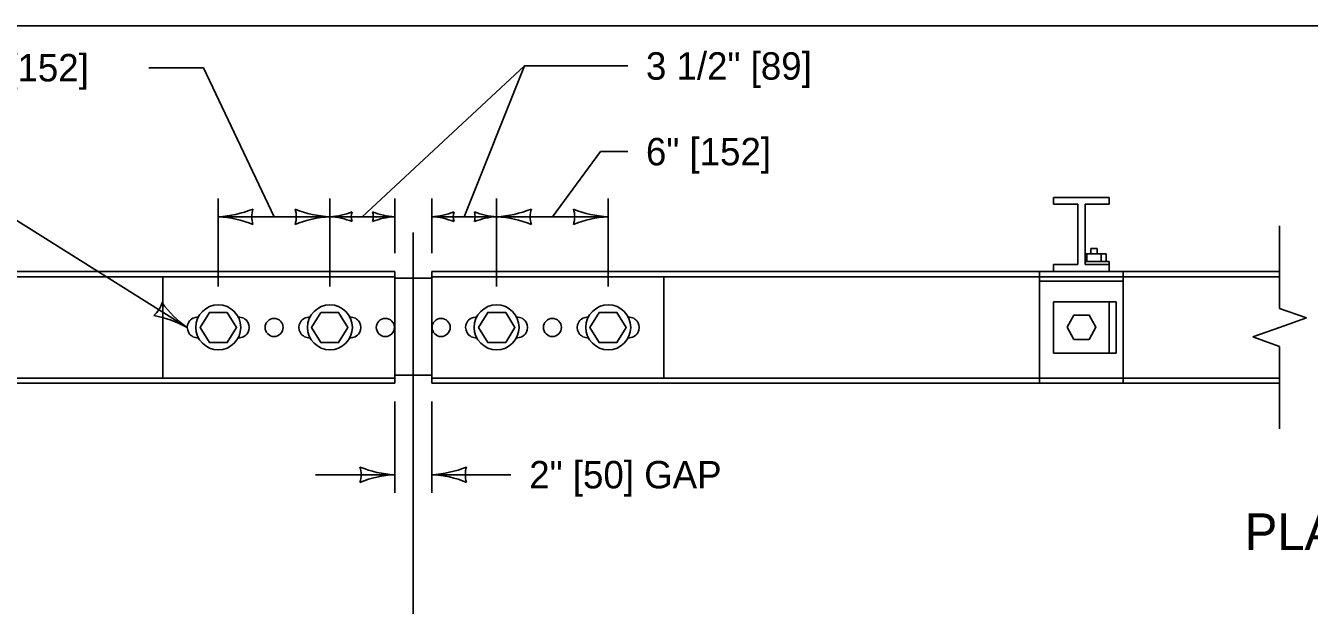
# Model space of a CAD drawing. Extents: x 49991.4 to 50021, y 49987.6 to 50011.4.
# Drawn here: x 50012.323 to 50015.133, y 50006.896 to 50008.165 of the extents above; entities that cross this region are included whole.
import ezdxf

# ---------------------------------------------------------------- set-up
doc = ezdxf.new("R2010")
doc.units = 0
for name, color, linetype in [('Level 1', 7, 'Continuous'), ('Level 2', 7, 'Continuous'), ('Level 3', 7, 'Continuous'), ('Level 4', 7, 'Continuous'), ('Level 5', 7, 'Continuous'), ('Level 6', 7, 'Continuous')]:
    doc.layers.add(name, color=color, linetype=linetype)

msp = doc.modelspace()

# ---------------------------------------------------------------- linework, layer by layer
at = {"layer": 'Level 1'}
for p, q in [((50014.5734, 50007.7742), (50014.5734, 50007.7888)), ((50014.5734, 50007.7888), (50014.6953, 50007.7888)), ((50014.6953, 50007.7742), (50014.6953, 50007.7888)), ((50014.5734, 50007.7742), (50014.6264, 50007.7742)), ((50014.6264, 50007.6422), (50014.6264, 50007.7742)), ((50014.6422, 50007.6422), (50014.6422, 50007.7742)), ((50014.6422, 50007.7742), (50014.6953, 50007.7742)), ((50014.5734, 50007.6422), (50014.6264, 50007.6422)), ((50014.5734, 50007.6264), (50014.5734, 50007.6422)), ((50014.6422, 50007.6649), (50014.6886, 50007.6649)), ((50014.6422, 50007.6485), (50014.695, 50007.6485)), ((50014.6422, 50007.6422), (50014.6953, 50007.6422)), ((50014.6462, 50007.6485), (50014.6462, 50007.6649)), ((50014.6777, 50007.6485), (50014.6777, 50007.6649)), ((50014.6886, 50007.6485), (50014.6886, 50007.6649)), ((50014.695, 50007.6422), (50014.695, 50007.6485)), ((50014.6953, 50007.6264), (50014.6953, 50007.6422)), ((50010.9506, 50007.6264), (50013.131, 50007.6264)), ((50013.131, 50007.3818), (50013.131, 50007.6264)), ((50013.131, 50007.6118), (50013.2122, 50007.6118)), ((50013.2122, 50007.3818), (50013.2122, 50007.6264)), ((50015.0681, 50007.6264), (50013.2122, 50007.6264)), ((50014.573, 50007.5601), (50014.71, 50007.5601)), ((50014.5732, 50007.4479), (50014.5732, 50007.5601)), ((50014.695, 50007.4479), (50014.695, 50007.5601)), ((50014.7102, 50007.4479), (50014.7102, 50007.5601)), ((50012.9692, 50007.4711), (50013.0083, 50007.4711)), ((50012.9693, 50007.4711), (50013.0084, 50007.4711)), ((50013.3739, 50007.4711), (50013.3348, 50007.4711)), ((50013.374, 50007.4711), (50013.3349, 50007.4711)), ((50014.573, 50007.4479), (50014.71, 50007.4479)), ((50013.131, 50007.3996), (50013.2122, 50007.3996)), ((50010.9506, 50007.3818), (50013.131, 50007.3818)), ((50015.0681, 50007.3818), (50013.2122, 50007.3818)), ((50014.1378, 50007.3818), (50015.0681, 50007.3818))]:
    msp.add_line(p, q, dxfattribs=at)
for points in [[(50020.9378, 50008.1646), (50009.7374, 50008.1646), (50009.7374, 49999.8856), (50020.9378, 49999.8856)], [(50012.7646, 50007.5371), (50012.7849, 50007.5041), (50012.7646, 50007.4711), (50012.7256, 50007.4711), (50012.7054, 50007.5041), (50012.7256, 50007.5371)], [(50012.9692, 50007.5371), (50012.949, 50007.5041), (50012.9692, 50007.4711), (50013.0083, 50007.4711), (50013.0286, 50007.5041), (50013.0083, 50007.5371)], [(50013.374, 50007.5371), (50013.3942, 50007.5041), (50013.374, 50007.4711), (50013.3349, 50007.4711), (50013.3147, 50007.5041), (50013.3349, 50007.5371)], [(50013.5786, 50007.5371), (50013.5583, 50007.5041), (50013.5786, 50007.4711), (50013.6176, 50007.4711), (50013.6378, 50007.5041), (50013.6176, 50007.5371)], [(50014.6179, 50007.4777), (50014.6514, 50007.4777), (50014.6661, 50007.5044), (50014.6514, 50007.5311), (50014.6179, 50007.5311), (50014.6033, 50007.5044)]]:
    msp.add_lwpolyline(points, close=True, dxfattribs=at)
for points in [[(50014.6546, 50007.6649), (50014.6546, 50007.6767)], [(50014.6546, 50007.6767), (50014.6687, 50007.6767)], [(50014.6687, 50007.6649), (50014.6687, 50007.6767)]]:
    msp.add_lwpolyline(points, dxfattribs=at)
for centre in [(50012.7449, 50007.5043), (50012.9892, 50007.5043), (50013.3541, 50007.5043), (50013.5985, 50007.5043)]:
    msp.add_circle(centre, 0.0492, dxfattribs=at)
for centre, start, end in [((50012.6997, 50007.504), 86.5998, 274.1511), ((50012.79, 50007.504), 265.8194, 265.8194), ((50012.79, 50007.504), 265.8703, 93.3787), ((50012.9441, 50007.504), 86.5869, 274.1639), ((50013.0343, 50007.504), 265.8831, 93.3659), ((50013.309, 50007.504), 86.5701, 274.1806), ((50013.3992, 50007.504), 265.8998, 93.349), ((50013.5533, 50007.504), 86.5572, 274.1934), ((50013.6436, 50007.504), 265.9126, 93.3361)]:
    msp.add_arc(centre, 0.0227, start, end, dxfattribs=at)
at = {"layer": 'Level 3'}
for p, q in [((50012.7123, 50008.0726), (50012.5925, 50008.0726)), ((50012.7123, 50008.0726), (50012.8669, 50007.7464)), ((50013.4152, 50008.0764), (50013.0601, 50007.7464)), ((50013.2831, 50007.7464), (50013.4152, 50008.0764)), ((50013.4152, 50008.0764), (50013.641, 50008.0764)), ((50013.4761, 50007.7464), (50013.5812, 50007.8889)), ((50013.5812, 50007.8889), (50013.641, 50007.8889)), ((50013.131, 50007.7464), (50012.9891, 50007.7464)), ((50013.3541, 50007.7464), (50013.2122, 50007.7464))]:
    msp.add_line(p, q, dxfattribs=at)
for points in [[(50012.677, 50007.5039), (50012.0896, 50007.8726)], [(50012.7448, 50007.5935), (50012.7448, 50007.7864)], [(50012.9892, 50007.5935), (50012.9891, 50007.7864)], [(50013.131, 50007.6664), (50013.131, 50007.7864)], [(50013.2122, 50007.6664), (50013.2122, 50007.7864)], [(50013.3541, 50007.5935), (50013.3541, 50007.7864)], [(50013.5984, 50007.5935), (50013.5984, 50007.7864)], [(50012.7448, 50007.7464), (50012.9891, 50007.7464)], [(50013.5984, 50007.7464), (50013.3541, 50007.7464)], [(50013.131, 50007.3418), (50013.131, 50007.1418)], [(50013.2122, 50007.3418), (50013.2122, 50007.1418)], [(50012.9576, 50007.1818), (50013.131, 50007.1818)], [(50013.2122, 50007.1818), (50013.3856, 50007.1818)]]:
    msp.add_lwpolyline(points, dxfattribs=at)
for centre, radius, start, end in [((50012.7333, 50007.9791), 0.233, 272.8273, 292.0772), ((50012.873, 50007.7464), 0.0548, 162.1388, 197.8612), ((50012.9983, 50007.9685), 0.2223, 247.456, 267.6395), ((50012.8609, 50007.7464), 0.0548, 342.1388, 17.8612), ((50012.9818, 50007.8953), 0.1491, 272.8273, 292.0772), ((50013.0712, 50007.7464), 0.0351, 162.1388, 197.8612), ((50013.1369, 50007.8886), 0.1423, 247.456, 267.6395), ((50013.0489, 50007.7464), 0.0351, 342.1388, 17.8612), ((50013.2048, 50007.8953), 0.1491, 272.8273, 292.0772), ((50013.2943, 50007.7464), 0.0351, 162.1388, 197.8612), ((50013.36, 50007.8886), 0.1423, 247.456, 267.6395), ((50013.2721, 50007.7464), 0.0351, 342.1388, 17.8612), ((50013.3426, 50007.9791), 0.233, 272.8273, 292.0772), ((50013.4823, 50007.7464), 0.0548, 162.1388, 197.8612), ((50013.6076, 50007.9685), 0.2223, 247.456, 267.6395), ((50013.4702, 50007.7464), 0.0548, 342.1388, 17.8612), ((50012.7356, 50007.5243), 0.2223, 67.456, 87.6395), ((50013.0006, 50007.5137), 0.233, 92.8273, 112.0772), ((50012.9833, 50007.6042), 0.1423, 67.456, 87.6395), ((50013.1384, 50007.5975), 0.1491, 92.8273, 112.0772), ((50013.2063, 50007.6042), 0.1423, 67.456, 87.6395), ((50013.3615, 50007.5975), 0.1491, 92.8273, 112.0772), ((50013.3449, 50007.5243), 0.2223, 67.456, 87.6395), ((50013.6099, 50007.5137), 0.233, 92.8273, 112.0772), ((50012.5684, 50007.572), 0.0548, 310.0235, 345.7459), ((50012.8028, 50007.6872), 0.2223, 215.3407, 235.5242), ((50012.563, 50007.3007), 0.233, 60.712, 79.9619), ((50013.1402, 50007.4039), 0.2223, 247.456, 267.6395), ((50013.0028, 50007.1818), 0.0548, 342.1388, 17.8612), ((50013.2007, 50007.4145), 0.233, 272.8273, 292.0772), ((50013.3404, 50007.1818), 0.0548, 162.1388, 197.8612), ((50013.1425, 50006.9491), 0.233, 92.8273, 112.0772), ((50013.203, 50006.9597), 0.2223, 67.456, 87.6395)]:
    msp.add_arc(centre, radius, start, end, dxfattribs=at)
at = {"layer": 'Level 4'}
for p, q in [((50010.9506, 50007.615), (50013.131, 50007.615)), ((50012.6233, 50007.3932), (50012.6233, 50007.615)), ((50015.0681, 50007.615), (50013.2122, 50007.615)), ((50013.72, 50007.3932), (50013.72, 50007.615)), ((50014.5427, 50007.3818), (50014.5427, 50007.6264)), ((50014.7256, 50007.3818), (50014.7256, 50007.6264)), ((50014.5428, 50007.6053), (50014.7256, 50007.6053)), ((50010.9506, 50007.3932), (50013.131, 50007.3932)), ((50015.0681, 50007.3932), (50013.2122, 50007.3932))]:
    msp.add_line(p, q, dxfattribs=at)
for centre in [(50012.867, 50007.504), (50013.1106, 50007.504), (50013.2327, 50007.504), (50013.4763, 50007.504)]:
    msp.add_circle(centre, 0.0198, dxfattribs=at)
at = {"layer": 'Level 5'}
msp.add_lwpolyline([(50013.1716, 50007.7118), (50013.1716, 50006.1981)], dxfattribs=at)
at = {"layer": 'Level 6'}
for p, q in [((50015.0681, 50007.7264), (50015.0681, 50007.5456)), ((50015.1266, 50007.5249), (50015.0681, 50007.5456)), ((50015.0681, 50007.5042), (50015.0096, 50007.4834)), ((50015.1266, 50007.5249), (50015.0681, 50007.5042)), ((50015.0681, 50007.4627), (50015.0096, 50007.4834)), ((50015.0681, 50007.4627), (50015.0681, 50007.2818))]:
    msp.add_line(p, q, dxfattribs=at)

# ---------------------------------------------------------------- texts
at = {"layer": 'Level 2'}
for s, height, p in [('6" [152]', 0.06, (50012.1876, 50008.0426)), ('3 1/2" [89]', 0.06, (50013.681, 50008.0464)), ('2" [50] GAP', 0.06, (50013.4256, 50007.1518)), ('PLAN', 0.08, (50014.9918, 50007.017))]:
    msp.add_text(s, height=height, dxfattribs=at).set_placement(p)
msp.add_text('6" [152]', height=0.06, rotation=360, dxfattribs=at).set_placement((50013.681, 50007.8589))

doc.saveas('drawing.dxf')
